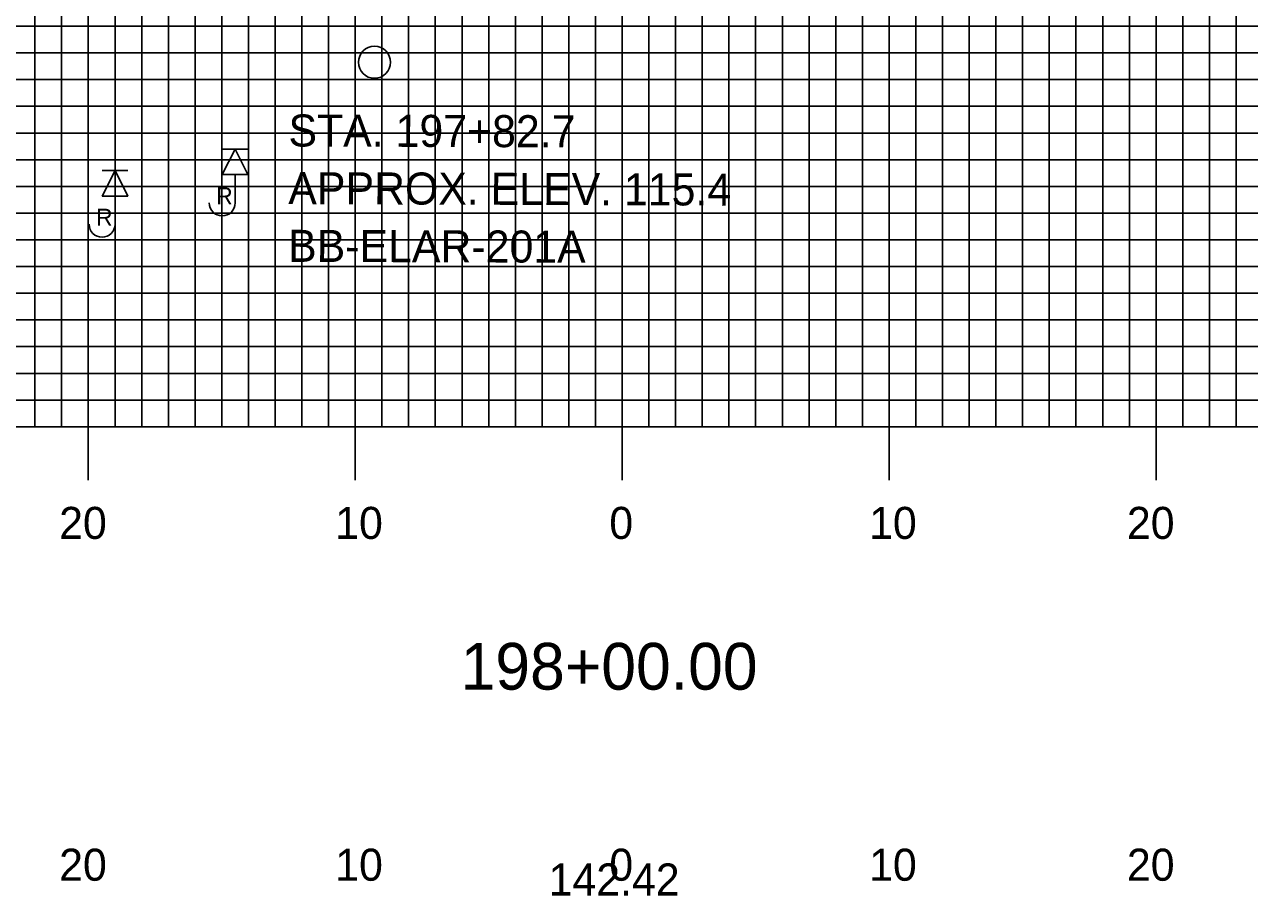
# Model space of a CAD drawing. Extents: x 1790124 to 1790467, y 442591 to 442811.
# Drawn here: x 1790267.31 to 1790313.2, y 442656.11 to 442688.73 of the extents above; entities that cross this region are included whole.
import ezdxf

# ---------------------------------------------------------------- set-up
doc = ezdxf.new("R2010")
doc.units = 0
for name, color, linetype in [('BORING - REFUSAL', 7, 'Continuous'), ('D_Roadway_Centerline_Text', 7, 'Continuous'), ('H_V ANNOTATION', 7, 'Continuous'), ('MAJOR', 7, 'Continuous'), ('MINOR', 7, 'Continuous'), ('S_Drainage_Invert', 7, 'Continuous')]:
    doc.layers.add(name, color=color, linetype=linetype)

msp = doc.modelspace()

# ---------------------------------------------------------------- linework, layer by layer
at = {"layer": 'BORING - REFUSAL'}
for p, q in [((1790275.676, 442684.065), (1790274.716, 442684.065)), ((1790271.176, 442683.265), (1790270.216, 442683.265)), ((1790275.196, 442683.106), (1790275.196, 442682.047)), ((1790270.696, 442682.306), (1790270.696, 442681.247))]:
    msp.add_line(p, q, dxfattribs=at)
for points in [[(1790275.196, 442684.065), (1790275.676, 442683.106), (1790274.716, 442683.106)], [(1790270.696, 442683.265), (1790271.176, 442682.306), (1790270.216, 442682.306)]]:
    msp.add_lwpolyline(points, close=True, dxfattribs=at)
for centre in [(1790274.711, 442682.047), (1790270.211, 442681.247)]:
    msp.add_arc(centre, 0.485, 180, 0, dxfattribs=at)
at = {"layer": 'MAJOR'}
for p, q in [((1790269.696, 442673.665), (1790269.696, 442718.665)), ((1790279.696, 442673.665), (1790279.696, 442718.665)), ((1790289.696, 442673.665), (1790289.696, 442718.665)), ((1790299.696, 442673.665), (1790299.696, 442718.665)), ((1790309.696, 442673.665), (1790309.696, 442718.665)), ((1790149.696, 442688.665), (1790429.696, 442688.665)), ((1790149.696, 442683.665), (1790429.696, 442683.665)), ((1790149.696, 442678.665), (1790429.696, 442678.665)), ((1790149.696, 442673.665), (1790429.696, 442673.665)), ((1790149.696, 442673.665), (1790429.696, 442673.665)), ((1790269.696, 442671.661), (1790269.696, 442673.665)), ((1790279.696, 442671.661), (1790279.696, 442673.665)), ((1790289.696, 442671.661), (1790289.696, 442673.665)), ((1790299.696, 442671.661), (1790299.696, 442673.665)), ((1790309.696, 442671.661), (1790309.696, 442673.665))]:
    msp.add_line(p, q, dxfattribs=at)
at = {"layer": 'MINOR'}
for p, q in [((1790267.696, 442673.665), (1790267.696, 442718.665)), ((1790268.696, 442673.665), (1790268.696, 442718.665)), ((1790270.696, 442673.665), (1790270.696, 442718.665)), ((1790271.696, 442673.665), (1790271.696, 442718.665)), ((1790272.696, 442673.665), (1790272.696, 442718.665)), ((1790273.696, 442673.665), (1790273.696, 442718.665)), ((1790274.696, 442673.665), (1790274.696, 442718.665)), ((1790275.696, 442673.665), (1790275.696, 442718.665)), ((1790276.696, 442673.665), (1790276.696, 442718.665)), ((1790277.696, 442673.665), (1790277.696, 442718.665)), ((1790278.696, 442673.665), (1790278.696, 442718.665)), ((1790280.696, 442673.665), (1790280.696, 442718.665)), ((1790281.696, 442673.665), (1790281.696, 442718.665)), ((1790282.696, 442673.665), (1790282.696, 442718.665)), ((1790283.696, 442673.665), (1790283.696, 442718.665)), ((1790284.696, 442673.665), (1790284.696, 442718.665)), ((1790285.696, 442673.665), (1790285.696, 442718.665)), ((1790286.696, 442673.665), (1790286.696, 442718.665)), ((1790287.696, 442673.665), (1790287.696, 442718.665)), ((1790288.696, 442673.665), (1790288.696, 442718.665)), ((1790290.696, 442673.665), (1790290.696, 442718.665)), ((1790291.696, 442673.665), (1790291.696, 442718.665)), ((1790292.696, 442673.665), (1790292.696, 442718.665)), ((1790293.696, 442673.665), (1790293.696, 442718.665)), ((1790294.696, 442673.665), (1790294.696, 442718.665)), ((1790295.696, 442673.665), (1790295.696, 442718.665)), ((1790296.696, 442673.665), (1790296.696, 442718.665)), ((1790297.696, 442673.665), (1790297.696, 442718.665)), ((1790298.696, 442673.665), (1790298.696, 442718.665)), ((1790300.696, 442673.665), (1790300.696, 442718.665)), ((1790301.696, 442673.665), (1790301.696, 442718.665)), ((1790302.696, 442673.665), (1790302.696, 442718.665)), ((1790303.696, 442673.665), (1790303.696, 442718.665)), ((1790304.696, 442673.665), (1790304.696, 442718.665)), ((1790305.696, 442673.665), (1790305.696, 442718.665)), ((1790306.696, 442673.665), (1790306.696, 442718.665)), ((1790307.696, 442673.665), (1790307.696, 442718.665)), ((1790308.696, 442673.665), (1790308.696, 442718.665)), ((1790310.696, 442673.665), (1790310.696, 442718.665)), ((1790311.696, 442673.665), (1790311.696, 442718.665)), ((1790312.696, 442673.665), (1790312.696, 442718.665)), ((1790149.696, 442687.665), (1790429.696, 442687.665)), ((1790149.696, 442686.665), (1790429.696, 442686.665)), ((1790149.696, 442685.665), (1790429.696, 442685.665)), ((1790149.696, 442684.665), (1790429.696, 442684.665)), ((1790149.696, 442682.665), (1790429.696, 442682.665)), ((1790149.696, 442681.665), (1790429.696, 442681.665)), ((1790149.696, 442680.665), (1790429.696, 442680.665)), ((1790149.696, 442679.665), (1790429.696, 442679.665)), ((1790149.696, 442677.665), (1790429.696, 442677.665)), ((1790149.696, 442676.665), (1790429.696, 442676.665)), ((1790149.696, 442675.665), (1790429.696, 442675.665)), ((1790149.696, 442674.665), (1790429.696, 442674.665))]:
    msp.add_line(p, q, dxfattribs=at)
at = {"layer": 'S_Drainage_Invert'}
msp.add_circle((1790280.415, 442687.316), 0.6, dxfattribs=at)

# ---------------------------------------------------------------- texts
at = {"layer": 'BORING - REFUSAL'}
for s, p in [('STA. 197+82.7', (1790277.193, 442684.162)), ('APPROX. ELEV. 115.4', (1790277.186, 442682.002)), ('BB-ELAR-201A', (1790277.179, 442679.842))]:
    msp.add_text(s, height=1.2, rotation=359.8142, dxfattribs=at).set_placement(p)
for p in [(1790274.487, 442681.991), (1790269.987, 442681.191)]:
    msp.add_text('R', height=0.64, dxfattribs=at).set_placement(p)
at = {"layer": 'D_Roadway_Centerline_Text'}
msp.add_text('142.42', height=1.2, dxfattribs=at).set_placement((1790286.94, 442656.112))
at = {"layer": 'H_V ANNOTATION'}
for s, height, p in [('20', 1.2, (1790268.604, 442669.465)), ('10', 1.2, (1790278.946, 442669.465)), ('0', 1.2, (1790289.214, 442669.465)), ('10', 1.2, (1790298.946, 442669.465)), ('20', 1.2, (1790308.604, 442669.465)), ('198+00.00', 1.75, (1790283.641, 442663.821)), ('20', 1.2, (1790268.604, 442656.665)), ('10', 1.2, (1790278.946, 442656.665)), ('0', 1.2, (1790289.214, 442656.665)), ('10', 1.2, (1790298.946, 442656.665)), ('20', 1.2, (1790308.604, 442656.665))]:
    msp.add_text(s, height=height, dxfattribs=at).set_placement(p)

doc.saveas('drawing.dxf')
